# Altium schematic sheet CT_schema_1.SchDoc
size 376 x 258 mm
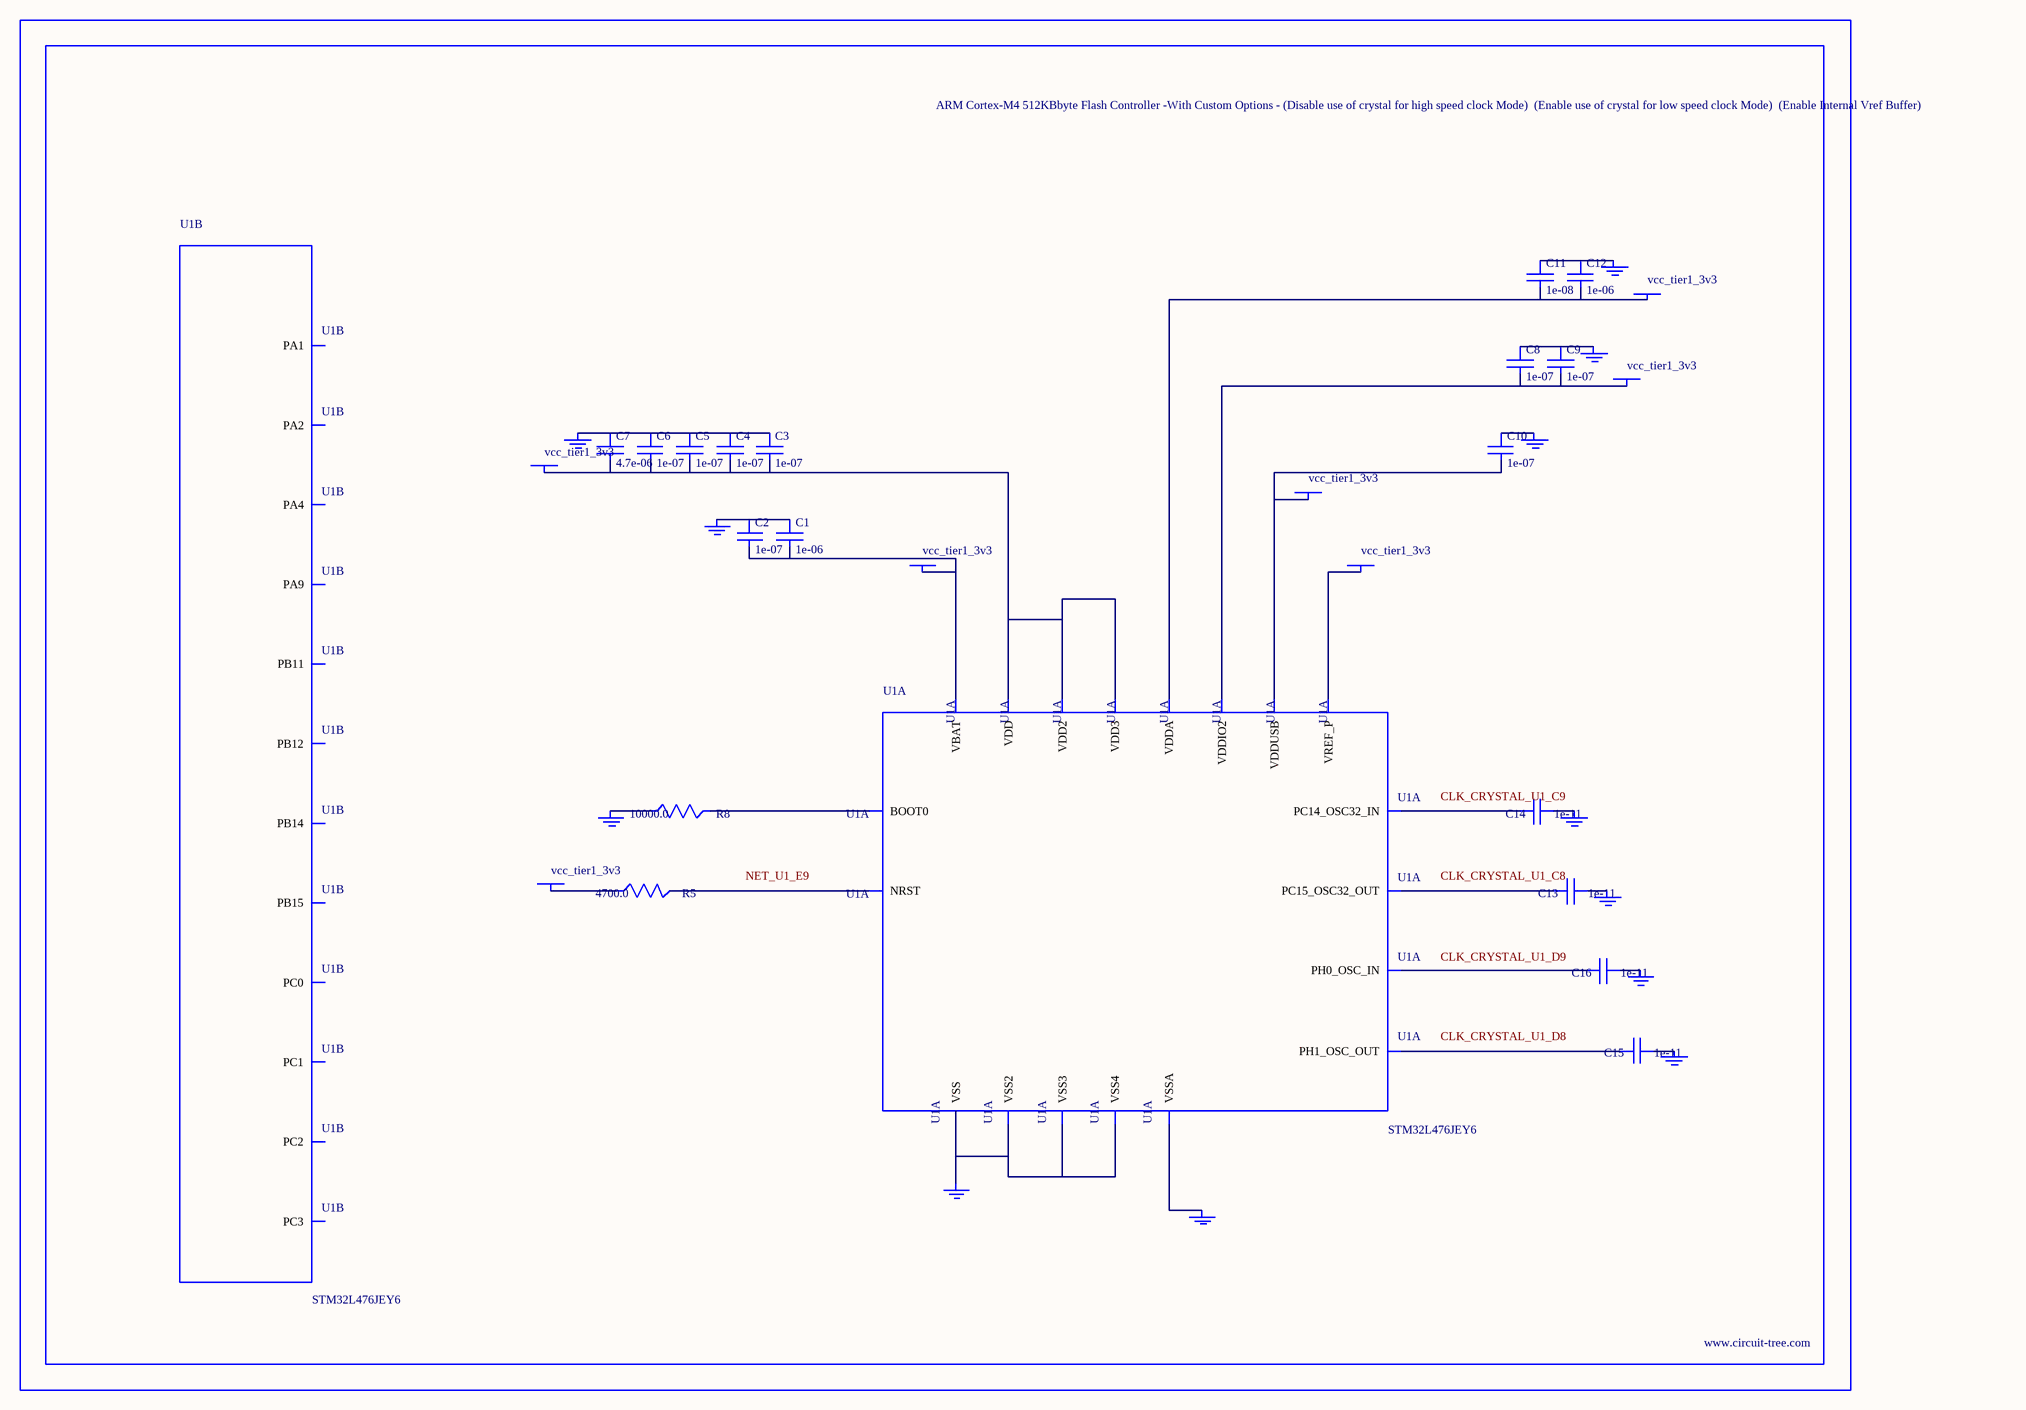
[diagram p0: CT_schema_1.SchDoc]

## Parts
BORDER0  (no value)
C1  1e-06  [C0603]
C2  1e-07  [C0603]
C3  1e-07  [C0603]
C4  1e-07  [C0603]
C5  1e-07  [C0603]
C6  1e-07  [C0603]
C7  4.7e-06  [C0603]
C8  1e-07  [C0603]
C9  1e-07  [C0603]
C10  1e-07  [C0603]
C11  1e-08  [C0603]
C12  1e-06  [C0603]
C13  1e-11  [C0402]
C14  1e-11  [C0402]
C15  1e-11  [C0402]
C16  1e-11  [C0402]
GND_INSTANCE_0_0  (no value)
GND_INSTANCE_0_1  (no value)
GND_INSTANCE_0_2  (no value)
GND_INSTANCE_0_3  (no value)
GND_INSTANCE_0_4  (no value)
GND_INSTANCE_0_5  (no value)
GND_INSTANCE_0_6  (no value)
GND_INSTANCE_0_7  (no value)
GND_INSTANCE_0_8  (no value)
GND_INSTANCE_0_9  (no value)
GND_INSTANCE_0_10  (no value)
GND_INSTANCE_0_11  (no value)
POWER_INSTANCE_0_0  vcc_tier1_3v3
POWER_INSTANCE_0_1  vcc_tier1_3v3
POWER_INSTANCE_0_2  vcc_tier1_3v3
POWER_INSTANCE_0_3  vcc_tier1_3v3
POWER_INSTANCE_0_4  vcc_tier1_3v3
POWER_INSTANCE_0_5  vcc_tier1_3v3
POWER_INSTANCE_0_6  vcc_tier1_3v3
R5  4700.0  [R0603]
R8  10000.0  [R0603]
U1  STM32L476JEY6  [WLCSP72]  (parts A,B of 6)

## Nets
NetC1_1: C1.1 C2.1 GND_INSTANCE_0_0.0(GND)
NetC1_2: C1.2 C2.2 POWER_INSTANCE_0_0.0(PWR) U1.B9(VBAT)
NetC3_1: C3.1 C4.1 C5.1 C6.1 C7.1 GND_INSTANCE_0_1.0(GND)
NetC3_2: C3.2 C4.2 C5.2 C6.2 C7.2 POWER_INSTANCE_0_1.0(PWR) U1.A9(VDD) U1.J1(VDD2) U1.J8(VDD3)
NetC8_1: C8.1 C9.1 GND_INSTANCE_0_2.0(GND)
NetC8_2: C8.2 C9.2 POWER_INSTANCE_0_2.0(PWR) U1.B6(VDDIO2)
NetC10_1: C10.1 GND_INSTANCE_0_4.0(GND)
NetC10_2: C10.2 POWER_INSTANCE_0_3.0(PWR) U1.A1(VDDUSB)
NetC11_1: C11.1 C12.1 GND_INSTANCE_0_5.0(GND)
NetC11_2: C11.2 C12.2 POWER_INSTANCE_0_4.0(PWR) U1.H9(VDDA)
NetC13_1: C13.1 GND_INSTANCE_0_6.0(GND)
NetC13_2: C13.2 U1.C8(PC15_OSC32_OUT)
NetC14_1: C14.1 GND_INSTANCE_0_7.0(GND)
NetC14_2: C14.2 U1.C9(PC14_OSC32_IN)
NetC15_1: C15.1 GND_INSTANCE_0_8.0(GND)
NetC15_2: C15.2 U1.D8(PH1_OSC_OUT)
NetC16_1: C16.1 GND_INSTANCE_0_9.0(GND)
NetC16_2: C16.2 U1.D9(PH0_OSC_IN)
NetGND_INSTANCE_0_3_0: GND_INSTANCE_0_3.0(GND) R8.1
NetGND_INSTANCE_0_10_0: GND_INSTANCE_0_10.0(GND) U1.G9(VSSA)
NetGND_INSTANCE_0_11_0: GND_INSTANCE_0_11.0(GND) U1.A8(VSS) U1.B1(VSS2) U1.J2(VSS3) U1.J9(VSS4)
NetPOWER_INSTANCE_0_5_0: POWER_INSTANCE_0_5.0(PWR) U1.G8(VREF_P)
NetPOWER_INSTANCE_0_6_0: POWER_INSTANCE_0_6.0(PWR) R5.1
NetR5_2: R5.2 U1.E9(NRST)
NetR8_2: R8.2 U1.D7(BOOT0)

Not connected (* = marked no-connect by the designer): U1 E3(PA9) F7(PC2) F8(PC1) F9(PC0) G1(PB15) G2(PB14) G3(PB11) G4(PA1) G5(PA4) G6(PA2) G7(PC3) H1(PB12)

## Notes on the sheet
- Labels drawn without touching a wire or pin: CLK_CRYSTAL_U1_C8, CLK_CRYSTAL_U1_C9, CLK_CRYSTAL_U1_D8, CLK_CRYSTAL_U1_D9, NET_U1_E9

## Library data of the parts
BORDER0 = BORDER_PAGE0
C1 C12 = C0603C105K3RACTU
C2-C6 C8-C10 = 06035C104K4Z2A
C7 = GRM188R6YA475KE15D
C11 = 06035C103K4Z2A
C13-C16 = C0402C100K3GACTU
GND_INSTANCE_0_0-GND_INSTANCE_0_11 = GND
POWER_INSTANCE_0_0-POWER_INSTANCE_0_6 = PWR
R5 = RC0603JR-074K7L
R8 = RC0603JR-0710KL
